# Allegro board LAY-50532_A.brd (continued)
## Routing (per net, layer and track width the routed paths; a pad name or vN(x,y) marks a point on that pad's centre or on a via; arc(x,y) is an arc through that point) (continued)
SWIN:
  vias: v1(113.45,61.94) v2(113.75,77.94) v2(115.19,77.92) v2(117.18,32.1) v2(117.18,31.09) v2(118.19,32.1) v2(118.19,31.09) v2(119.21,32.1) v2(119.21,31.09) v2(119.89,42.79) v2(119.86,40.98) v2(119.86,39.96) v2(119.85,38.69) v2(119.85,37.67) v2(119.85,36.65) v2(120.22,32.1) v2(120.22,31.09) v2(121.86,33.58) v2(121.97,31.61)
SYNCINMODE_IC: length 23.6
  TOP w0.14: U5.31 109.86,57.43 v1(109.03,56.61) ; R78.2 91.45,56.63 v1(91.45,56.64) 91.45,59.39 J5.2
  BOTTOM w0.14: v1(109.03,56.61) 106.35,56.61 105.43,55.69 92.39,55.69 v1(91.45,56.64)
VDIG: length 6.1
  TOP w0.14: U5.28 105.97,58.93 v1(105.04,58)
  BOTTOM w0.14: C10.1 v1(105.04,58)
VMON1: length 53.9
  TOP w0.14: U5.16 114.72,61.35 115.16,61.79 v1(115.96,61.79) 115.98,61.81 117.9,61.81 119.23,63.13 119.23,72.08 126.78,79.63 VMON1.1 R37.1 R32.2
  BOTTOM w0.14: v1(115.96,61.79) 115.98,61.81 C32.1
VMON1_CONN: length 18.8
  TOP w0.14: R32.1 126.78,109.15 127.63,110 140.33,110 140.97,110.64 TP19.1
VMON2: length 17.1
  TOP w0.14: v1(119.67,60.92) 115.98,60.92 v1(115.98,60.92) 115.98,60.71 115.2,59.93 114.72,59.93 U5.15 ; VMON2.1 128.5,61.84 127.77,61.84 v1(127.72,61.84)
  BOTTOM w0.14: v1(119.67,60.92) R38.1 120.41,61.83 R33.2 120.41,62.48 120.57,62.64 126.92,62.64 v1(127.72,61.84) ; C33.1 v1(115.98,60.92)
VMON2_CONN: length 56.5
  L3_INT1 w0.114: v2(122.22,61.83) 120.49,63.57 120.49,72.69 121.91,74.11 121.91,106.44 TP20.1
  BOTTOM w0.14: v2(122.22,61.83) R33.1
VMON3_CONN: length 30.9
  TOP w0.14: v1(134.24,93.56) R34.1
  L3_INT1 w0.114: TP21.1 147.62,113.38 134.24,100 v1(134.24,93.56)
VMON3_R: length 3.7
  TOP w0.14: 134.24,90.93 R34.2 137.01,91.82 J12.7
VMON4_CONN: length 30.6
  TOP w0.14: R35.1 v1(144.41,93.57)
  L3_INT1 w0.114: v1(144.41,93.57) 144.41,99.15 158.65,113.38 TP22.1
VMON4_R: length 3.6
  TOP w0.14: R40.1 R35.2 144.42,91.82 J13.7
N17950540: length 33.6
  TOP w0.14: R65.1 v1(62.15,77.65)
  BOTTOM w0.14: J6.12 58.45,48.32 60.69,50.57 60.69,77.16 61.18,77.65 v1(62.15,77.65)
N17950546: length 32.1
  TOP w0.14: R66.1 v1(62.16,74.12)
  BOTTOM w0.14: v1(62.16,74.12) 61.12,73.08 61.12,48.48 58.43,45.78 J6.10
N17950552: length 38.6
  TOP w0.14: R78.1 v1(89.56,55.56)
  BOTTOM w0.14: J6.8 64.03,43.24 71.96,51.17 76.25,51.17 77.58,52.5 86.5,52.5 v1(89.56,55.56)
N18041286: length 4.9
  TOP w0.14: SW1.2 77.96,84.27 77.97,84.26 v1(78.16,84.26)
  BOTTOM w0.14: R2.2 C3.1 v1(78.16,84.26)
N18053281: length 4.9
  TOP w0.14: SW2.2 v1(78.16,70.63)
  BOTTOM w0.14: v1(78.16,70.63) C5.1 R6.2
N18177905: length 8.5
  TOP w0.14: R45.1 71.29,28.48 71.3,28.48 C45.1 74.56,28.48 U3.1 74.6,27.49 75.01,27.08 v1(75.51,27.08) 76.06,27.08 76.5,27.52 U3.3
N18177915: length 4.5
  TOP w0.14: C46.1 R46.2 R50.1 74.6,32.91 U3.5
N18177949: length 8.4
  TOP w0.14: U3.4 76.59,31.53 v1(76.59,33.16) R50.2
  BOTTOM w0.14: v1(76.59,33.16) 78.47,35.04 78.47,36.3 J30.2
N18177998: length 2.7
  TOP w0.14: J30.3 79.84,35.13 R51.1
N18178006: length 2.7
  TOP w0.14: R52.1 78.86,40.21 78.87,40.22 J30.1
N18178603: length 15.6
  TOP w0.14: C47.1 90.7,26.65 U4.3 88.41,27.5 88.18,27.73 86.72,27.73 86.51,27.52 U4.1 v1(86.51,21.99) SW3.2
N18178669: length 2.7
  TOP w0.14: U4.4 88.41,31.21 88.39,31.23 R54.1 R53.2
N18196092: length 4.6
  TOP w0.14: J73.18 58.39,77.74 59.31,76.82 R67.1
N18196101: length 4.2
  TOP w0.14: J73.20 R64.1
N18229657: length 1.5
  TOP w0.14: R47.2 D7.A
N18229660: length 1.7
  TOP w0.14: D7.C Q2.3
N18229791: length 1.7
  TOP w0.14: D8.C Q3.3
N18230808: length 1.5
  TOP w0.14: R48.2 D8.A
N18230892: length 1.7
  TOP w0.14: D9.C Q4.3
N18230895: length 1.5
  TOP w0.14: D9.A R49.2
N18266548: length 12.4
  TOP w0.521: 38.08,3.92 J92.1 41.61,3.92 ; J92.2 41.15,16.14 ; J92.2 38.53,18.76 ; J92.2 38.53,16.14 ; J92.2 41.15,18.76
N18368184: length 1.6
  TOP w0.508: R79.2 R12.1
N18377789: length 1.9
  BOTTOM w0.508: R13.1 C51.2
N18378672: length 4.5
  BOTTOM w0.508: R76.2 131.65,50.52 R74.1 133.27,51.12 132.99,51.4 C52.1 132.98,51.87 R3.2
N18406944: length 6.5
  TOP w0.305: R79.3 143.56,47.17 142.34,45.96 R75.1
N18465771: length 4.3
  TOP w0.254: RCOMP1.1 CHF1.1 J94.1
N18465820: length 4.4
  TOP w0.254: J94.3 CHF2.1 RCOMP2.1
N18465826: length 1.4
  TOP w0.254: CCOMP1.1 103.91,36.01 RCOMP1.2
N18465873: length 1.6
  TOP w0.254: CCOMP2.1 RCOMP2.2
N18468740: length 9.2
  TOP w0.14: R30.2 96.67,71.99 97.09,72.41 TP23.1 C42.1
N18472203: length 2.4
  TOP w0.14: U5.17 114.17,61.76 v1(114.34,61.94)
  BOTTOM w0.508: v1(114.34,61.94) 114.34,61.6 C12.1

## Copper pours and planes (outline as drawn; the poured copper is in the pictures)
GND on TOP: 0.64,116.46 174.5,116.46 174.5,68.14 173.95,68.14 174.5,68.14 174.5,49.69 154.01,49.69 152.58,48.25 152.58,43.45 151.75,42.62 142.86,42.62 142.86,42.04 152.59,42.04 153.52,42.97 153.52,48.22 154.29,48.99 174.5,48.99 174.5,0.63 0.64,0.63 ; 11 cut-outs
GND on BOTTOM: 0.63,0.63 0.63,116.46 174.5,116.46 174.5,0.63 ; 7 cut-outs
GND on L2_GND1, L5_GND2, L7_GND3: 0.64,0.64 0.64,116.46 174.5,116.46 174.5,0.64
GND on L3_INT1: 0.64,0.63 0.64,116.46 174.5,116.46 174.5,0.63 ; 1 cut-out
GND on L4_PWR1: 0.64,0.63 0.64,116.46 174.5,116.46 174.5,0.63
GND on L6_PWR2: 0.64,0.64 0.64,116.46 174.5,116.46 174.5,0.64 ; 2 cut-outs
VBAT on TOP: 111.12,19.09 111.12,2.41 112.84,0.68 130.22,0.68 130.46,0.92 130.46,7.23 130.11,7.58 124.27,7.58 123.65,8.2 123.65,18.32 122.11,19.86 111.89,19.86
VBAT_S on TOP: 68.76,86.02 66.62,86.02 66.37,85.77 66.37,83.01 66.6,82.78 68.45,82.78 69.04,83.37 69.04,85.75
VBAT_S on TOP: 68.74,72.29 66.6,72.29 66.34,72.03 66.34,69.27 66.58,69.04 68.42,69.04 69.02,69.63 69.02,72.01
VBAT_S on TOP: 116.68,24.95 133.62,24.94 135.91,22.65 135.91,3.34 135.85,3.29 130.85,3.29 130.85,3.29 130.85,7.97 130.85,20.9 129.51,22.23 114.13,22.23 113.76,22.6 113.76,23.97 113.94,24.15 115.88,24.15
VBAT_S on L3_INT1: 121.94,22.45 121.57,22.09 66.98,22.09 65.86,23.2 65.86,85.35 66.65,86.14 71.43,86.14 72.67,84.9 72.67,34.21 78.46,28.42 120.53,28.42 121.94,27.02
VIN on L4_PWR1: 116.22,25.94 121.71,25.94 122.1,25.55 122.1,22.3 121.9,22.09 112.02,22.09 103.45,30.66 103.45,56.84 97.5,62.79 97.5,68.19 95.45,70.23 95.45,73.9 95.6,74.05 99.19,74.05 100.25,72.99 100.25,69.45 109.64,60.06 109.64,56.39 108.59,55.35 108.59,51 109.64,49.95 109.64,32.52
BIAS_IN_CON on TOP: 56.39,116.45 64.26,116.45 64.77,115.94 64.77,98.09 63.53,96.85 51.36,96.85 51.06,97.15 51.06,100.68 51.83,101.45 55.18,101.45 56.09,102.36 56.09,116.15
Net_3 on TOP (solid shape): outline of 172 points within 100.32,46.48 104.32,50.48
Net_4 on TOP (solid shape): outline of 172 points within 100.32,66.88 104.32,70.88
Net_5 on TOP (solid shape): outline of 172 points within 120.52,66.88 124.52,70.88
Net_6 on TOP (solid shape): outline of 172 points within 120.52,46.48 124.52,50.48
SW1LX1 on TOP: 112.79,60.67 112.79,66.75 112.74,66.79 112.74,76.05 111.83,76.97 105.51,76.97 104.56,76.02 104.56,62.76 104.83,62.5 111.62,62.5 112.02,62.1 112.02,60.64 112.07,60.59 112.71,60.59
SW1OUT on TOP: 99.18,116.46 115.5,116.46 115.51,116.46 115.72,116.46 115.93,116.24 115.93,82.02 115.85,81.94 113.51,81.94 113.17,81.59 113.17,79.45 112.44,78.72 103.48,78.72 102.58,79.62 102.58,80.59 102.36,80.81 100.22,80.81 99.18,81.85
SW1OUT on L6_PWR2: 99.18,116.46 115.5,116.46 115.5,82.19 115.34,82.02 114.08,82.02 111.45,79.39 111.43,79.39 110.96,78.93 100.26,78.93 99.18,80.01
SW2LX on TOP: 129.37,59.54 129.37,59.43 129.46,59.34 129.46,58.27 129.47,58.26 131.64,58.26 131.68,58.23 131.68,54.74 128.24,51.3 128.24,44.6 128.64,44.2 131.37,44.2 131.49,44.32 131.49,48.48 133.41,50.4 133.41,55.87 133.81,56.27 137.01,56.27 137.81,55.47 137.81,54.64 137.83,54.62 142.91,54.62 143.38,55.09 143.38,59.63 142.33,60.67 130.51,60.67
SW2OUT on TOP: 143.78,46.4 143.22,45.84 143.22,43.16 143.76,42.62 151.75,42.62 152.58,43.45 152.58,48.25 154.01,49.69 174.5,49.69 174.5,67.84 174.45,67.89 170.2,67.89 168.8,66.48 168.8,64.93 168.36,64.49 149.83,64.49 146.96,61.61 146.96,51.85 146.7,51.59 135.21,51.59 134.59,50.97 134.59,50.12 135.25,49.46 146.69,49.46 147.04,49.11 148.45,49.11 148.81,48.74 148.81,47.03 148.18,46.4
SW2OUT on L4_PWR1: 168.75,67.89 174.45,67.89 174.5,67.84 174.5,49.47 151.52,49.47 150.24,48.18 150.24,44.2 148.66,42.62 143.49,42.62 143.22,42.89 143.22,45.84 143.78,46.4 146.94,46.4 146.95,46.41 146.95,49.4 146.96,49.41 146.96,61.51 148.12,62.68 152.31,62.68 152.51,62.88 152.51,62.88 154.34,64.71 168.06,64.71 168.46,65.11 168.46,67.6
SW2OUT on L6_PWR2: 135.28,49.47 146.88,49.47 147.03,49.32 147.03,46.5 146.94,46.4 143.78,46.4 143.22,45.84 143.22,42.89 143.49,42.62 148.66,42.62 150.24,44.2 150.24,48.18 151.52,49.47 174.5,49.47 174.5,49.47 174.5,67.84 174.45,67.89 170.36,67.89 168.81,66.34 168.81,65.13 168.21,64.53 150.15,64.53 146.9,61.29 146.9,51.76 146.76,51.62 135.42,51.62 134.81,51 134.81,49.94
SWIN on TOP: 122.82,34.36 122.82,28.79 122.09,28.07 112.71,28.07 112.71,39.47 117.58,44.33 117.58,55.63 119.79,57.83 131.04,57.83 131.39,57.49 131.39,55.24 131.19,55.04 127.4,55.04 127.19,54.83 126.86,54.5 126.86,45.53 124.75,43.41 122.64,43.41 122.32,43.1 122.32,34.85
SWIN on TOP: 114.96,62.48 114.22,62.48 113.82,62.08 113.82,60.65 113.74,60.57 113.11,60.57 113.05,60.63 113.05,78.13 113.51,78.6 113.51,81.52 113.61,81.62 115.87,81.62 116.05,81.44 116.05,63.56
SWIN on L4_PWR1: 132.31,68.88 132.31,28.43 132.07,28.19 116.3,28.19 115.98,28.51 115.98,43.16 112.93,46.21 112.93,68.6 113.47,69.13 132.06,69.13
SWIN on L6_PWR2: 114,81.43 115.72,81.43 115.92,81.23 115.92,74.02 115.9,74 113.56,74 113.01,74.54 113.01,80.44
N18266548 on TOP: 85.96,11.91 87.06,11.91 87.06,11.9 87.06,5 84.84,2.78 43.73,2.78 41.61,0.66 38.02,0.66 37.67,1.02 37.67,18.92 38.06,19.32 41.76,19.32 42.32,18.76 42.32,5.15 42.89,4.59 84.74,4.59 85.96,5.81 85.96,11.91
N18367835 on TOP: 132.63,47.7 132.63,44.13 133.37,43.39 136.69,43.39 136.88,43.57 136.88,44.74 137.47,45.33 140.15,45.33 140.27,45.45 140.27,48 139.93,48.34 133.27,48.34

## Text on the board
BOTTOM: 11 OF 14 | L8_SS | 170-50532 REV A
Board Geometry/Soldermask Bottom: 12 OF 14 | SECONDARY SOLDERMASK
Ref Des/Silkscreen Bottom: 13 OF 14 | SECONDARY SILKSCREEN
User.Comments: 1 OF 1 | TEST PROBE | 1/1 | 1 | 2
TOP: 4 OF 14 | L1_PS
Board Geometry/Soldermask Top: 3 OF 14 | PRIMARY SOLDERMASK
Ref Des/Silkscreen Top: SDA | FS0B | BIAS_IN_CON | BIAS_IN | GND | VDDIO_REG | VDDIO | VCC | EN2_IC | EN1_IC | EN2_R | EN1_R | EN2 | FS0B_VIN | FS0B_IC | SYNCINMODE_IC | V7P5_REG | VDDOTP | 2 OF 14 | PRIMARY SILKSCREEN | X-KITFS5600SKTEVM
L2_GND1: 5 OF 14 | L2_GND1
L3_INT1: 6 OF 14 | L3_INT1
L4_PWR1: 7 OF 14 | L4_PWR1
L5_GND2: 8 OF 14 | L5_GND2
L6_PWR2: 9 OF 14 | L6_PWR2
L7_GND3: 10 OF 14 | L7_GND3
XSECTION_CHART: *  SURFACE - AIR 0 MIL | *  DIELECTRIC - LPI 0.7 MIL | L1 TOP CONDUCTOR - 2OZ_COPPER 2.9 MIL | *  DIELECTRIC - TU-662 3.72 MIL | L2 L2_GND1 PLANE - 1OZ_COPPER 1.4 MIL | *  DIELECTRIC - TU-662 4 MIL | L3 L3_INT1 CONDUCTOR - 1OZ_COPPER 1.4 MIL | *  DIELECTRIC - TU-662 12.6 MIL | L4 L4_PWR1 PLANE - 1OZ_COPPER 1.4 MIL | L5 L5_GND2 PLANE - 1OZ_COPPER 1.4 MIL | *  DIELECTRIC - TU-662 13.44 MIL | L6 L6_PWR2 PLANE - 1OZ_COPPER 1.4 MIL | L7 L7_GND3 PLANE - 1OZ_COPPER 1.4 MIL | L8 BOTTOM CONDUCTOR - 2OZ_COPPER 2.9 MIL | DESIGN CROSS SECTION CHART | ___________________________ | TOTAL THICKNESS 61.08 MIL | 1-8
DIMENSION: SECONDARY DATUM | SKT U5 PIN 1 | SEE DETAIL C | SCALE: NONE | LAYERS | L1_PS | L3_INT1 | L8_SS | TRACE WIDTH | 5.50 | 4.50 | SE | IMPEDANCE | 50.00 | REFERENCE LAYER | DIFF | 2,4 | 2 | 5 | BOARD THICKNESS TOLERANCE +/-10% | 22. THIS BOARD USES VIA-IN-PAD: SEE FAB_VIAFILL.ART | A. ALL VIAS USING X.1 DRILL SIZES ARE TO BE FILLED WITH NON-CONDUCTIVE VIA FILL. | B. OVERPLATE THE FILLED VIA AND APPLY FINISH METAL TREATMENT. | C. DIMPLE OR PROTRUSION ON VIA-IN-PADS MUST BE NO GREATER THAN .001". | LACKWERKE-PETERS PP2795 OR EQUIVALENT AND MADE PLANAR TO THE PADS. | A. BOTH SIDES GOLD: 2-15 MICROINCHES OF GOLD OVER 100-350 MICROINCHES NICKEL. | B. SELECTIVE AREA (32 PINS QFN): TOTAL 45-55 MICROINCHES HARD GOLD OVER 100-350 MICROINCHES NICKEL. | 19 | 7B | 16 | 22 | 8 | DETAIL | LAYER STACKUP | IMPEDANCE REQUIREMENTS | IMPEDANCE TOLERANCE IS 10% | PRIMARY DATUM | GRID ORIGIN | A | C | B
PASTEMASK_TOP: 1 OF 14 | PASTEMASK TOP
User.5: 14 OF 14 | SECONDARY PASTEMASK
User.14: 22. THIS FAB_VIAFILL.ART SHOWS LOCATIONS OF VIA-IN-PAD TO BE FILLED. | 2/2 | 2
User.15: ALL PARTS, MATERIALS AND FINISHED | ASSEMBLY SHALL NOT CONTAIN ANY OF | THE SUBSTANCES OF VERY HIGH CONCERN | (SVHC) ABOVE THE THRESHOLD VALUE PER | THE CURRENT ECHA LIST OF SVHC'S AND | WITH ANNEX XIV AND ANNEX XVII OF REACH | DIRECTIVE 76/769/EEC. A CERTIFICATE OF | COMPLIANCE IS REQUIRED UPON REQUEST. | ASSEMBLY SHALL MEET THE RoHS | COMMISSION DELEGATED DIRECTIVE (EU) | 2015/863 OF 31 MARCH  2015 AMENDING | ANNEX II TO DIRECTIVE 2011/65/EU. A | CERTIFICATE OF COMPLIANCE IS | REQUIRED UPON REQUEST. | DELEEP | ORIGINAL RELEASE
User.20: TP4 | TP1 | TP5 | TP2 | TP6 | TP3 | TP7 | C2 | C1 | R2 | C4 | C5 | R7 | C6 | C7 | R8 | C8 | C3 | R9 | R11 | C9 | C10 | R12 | C12 | C13 | R18 | C22 | R38 | C21 | R34 | C24 | R43 | C25 | R39 | R40 | R41 | R46 | R47 | R50 | C31 | C35 | C37 | R56 | R57 | C40 | C41 | C39 | R62 | C43 | C49 | C50 | R66 | C48 | R68 | J13 | J15 | J16 | J18 | J21 | 16 | 2 | J1 | RESET | J2 | LLWU | 20 | SW1 | 1 | 19 | R1 | SDA | 15 | USB | RF | R5 | R13 | GND | ACCEL | D2 | U6 | D3 | RGB | R25 | R27 | R28 | U8 | R30 | C16 | FLEXIO | R32 | R36 | R37 | X1 | C20 | R33 | C23 | JTAG | 8 | C29 | C26 | R42 | C27 | R48 | 9 | U11 | R53 | R52 | TP18 | 5 | 4 | C33 | C36 | SPI FLASH | R55 | R59 | U15 | U12 | D4 | U16 | U13 | A | K82F | U14 | C | TP19 | C44 | R67 | D7 | Y2 | Y1 | C52 | C47 | C53 | D8 | C51 | SWD | D5 | D6 | D11 | 10 | J24 | BT | D9 | D10 | D12 | D13 | 11 | C57 | 12 | NMI | J3 | J4 | SW3 | J23 | 3 | TP9 | L2 | U10 | J9 | SH1 | 100 | 76 | 75 | L3 | J10 | TP21 | TP20 | L4 | 25 | 51 | 26 | 50 | J17 | J14 | U17 | J19 | TP22 | J20 | SW2 | R6 | R10 | R21 | R22 | TP11 | U4 | R29 | R31 | C15 | TP14 | C19 | TP15 | TP16 | C18 | R35 | C34 | R63 | R64 | R65 | D1 | R3 | TP8 | R4 | R15 | R16 | C11 | TP10 | R14 | R19 | R20 | R17 | R26 | C14 | U1 | U2 | U3 | C17 | R23 | R24 | 14 | U7 | U5 | 13 | TP13 | U9 | TP17 | R45 | C30 | C28 | C32 | R51 | R54 | R58 | 6 | C38 | R60 | R61 | C42 | C45 | C46 | C54 | C55 | C56 | L1 | 32 | J6 | J7 | J8 | 17 | TP12 | E2 | E1 | J22 | J5 | 7 | J12 | J11 | 18 | FRDM-K82F | + | -
User.24: R68 | C48 | R66 | C49 | C50 | R62 | C43 | C39 | C40 | C41 | R56 | R57 | C37 | C35 | C31 | R50 | R46 | R47 | C25 | R39 | R40 | R41 | R43 | C24 | C21 | R34 | R38 | C22 | R18 | C12 | C13 | C4 | C5 | R7 | C6 | C7 | R8 | C8 | C3 | R9 | R11 | C9 | C10 | R12 | C2 | C1 | R2 | TP4 | TP1 | TP5 | TP2 | TP6 | TP3 | TP7 | J21 | J18 | J16 | J15 | J13 | J4 | J3 | 16 | 2 | NMI | 12 | C57 | 1 | D12 | D13 | 11 | C | 15 | A | D9 | D10 | 9 | J24 | BT | 4 | 10 | D11 | D5 | D6 | C51 | SWD | D8 | C53 | Y1 | C52 | C47 | Y2 | D7 | USB | R67 | K82F | C44 | TP19 | U14 | 5 | U13 | U16 | D4 | U12 | U15 | 8 | R59 | R55 | SPI FLASH | C36 | C33 | TP18 | R52 | R53 | U11 | R48 | C27 | C29 | C26 | R42 | JTAG | C23 | SDA | X1 | C20 | R33 | R36 | R37 | R32 | FLEXIO | C16 | R30 | U8 | R28 | R27 | R25 | D3 | RGB | U6 | D2 | ACCEL | GND | R13 | R5 | RF | R1 | 19 | SW1 | 20 | LLWU | RESET | J2 | J1 | SW2 | J20 | 3 | TP22 | J19 | U17 | J14 | J17 | 50 | 26 | 25 | 51 | L4 | TP20 | TP21 | J10 | L3 | 75 | 100 | 76 | SH1 | J9 | U10 | L2 | TP9 | J23 | SW3 | R63 | R64 | R65 | C34 | R35 | C18 | TP15 | TP16 | C19 | C15 | TP14 | R29 | R31 | U4 | TP11 | R21 | R22 | R10 | R6 | TP12 | C56 | C55 | C54 | C46 | C45 | C42 | R61 | R60 | C38 | 6 | R58 | R54 | R51 | C32 | C28 | C30 | R45 | TP17 | U9 | TP13 | U5 | 13 | U7 | 14 | C17 | R23 | R24 | U1 | U2 | U3 | C14 | R26 | R17 | R14 | R19 | R20 | TP10 | C11 | TP8 | R4 | R15 | R16 | R3 | D1 | 17 | J6 | J7 | J8 | 32 | L1 | E1 | E2 | 18 | J11 | J12 | 7 | J5 | J22 | FRDM-K82F | + | -
User.36: FIGURE | FINISHED_SIZE | 8.0 | 10.0 | 10.1 | 40.0 | 43.0 | 63.0 | 76.0 | 59.0 | 79.0 | 125.0 | DRILL CHART: TOP to BOTTOM | ALL UNITS ARE IN MILS | TOLERANCE_DRILL | +0.0/-8.0 | +0.0/-10.0 | +0.0/-10.1 | +3.0/-3.0 | +2.0/-2.0 | +1.0/-1.0 | PLATED | NON-PLATED | QTY | 60 | 560 | 9 | 90 | 24 | 11 | 16 | 3 | 5 | 4 | 782 | TOTAL HOLES:
